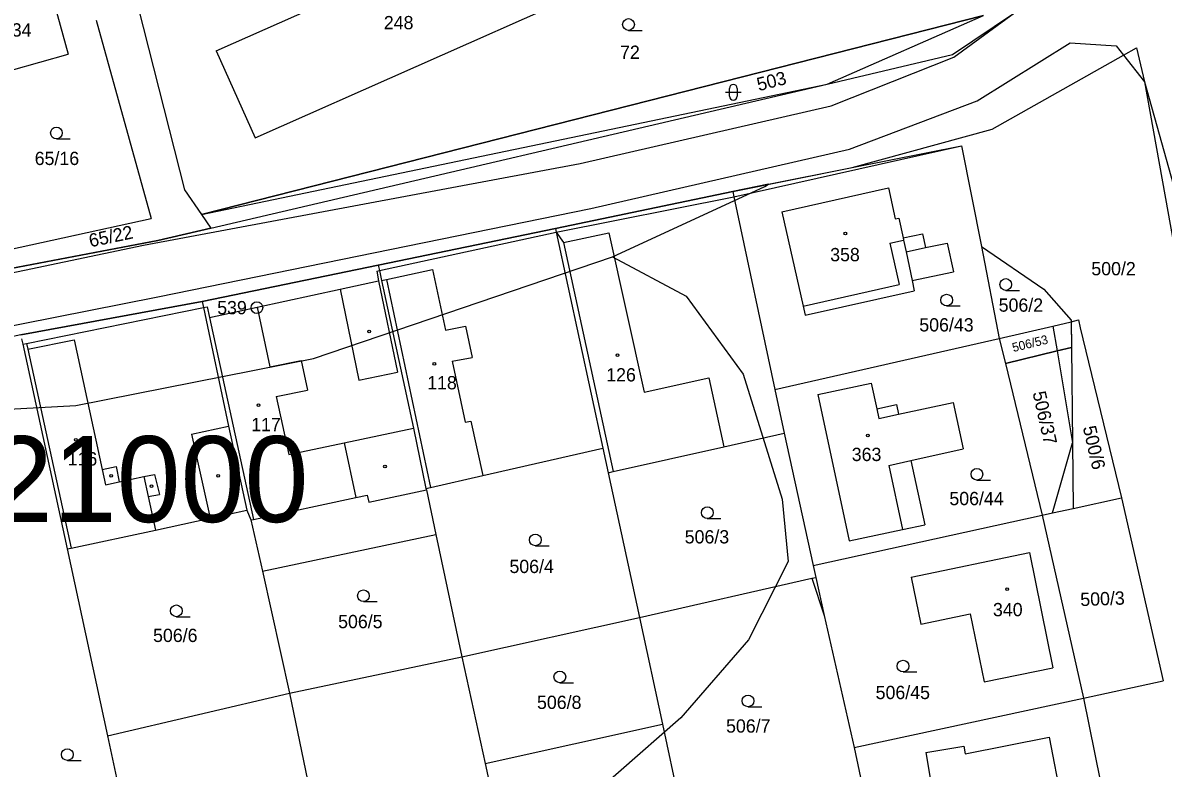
# Model space of a CAD drawing. Extents: x -725765 to -723182, y -1052705 to -1049154.
# Drawn here: x -724834.1 to -724688.1, y -1051176.5 to -1051081 of the extents above; entities that cross this region are included whole.
import ezdxf

# ---------------------------------------------------------------- set-up
doc = ezdxf.new("R2010")
doc.units = 0
for name, color, linetype in [('Vrstva 1', 7, 'Continuous'), ('Vrstva 17', 7, 'Continuous'), ('Vrstva 18', 7, 'Continuous'), ('Vrstva 19', 7, 'Continuous'), ('Vrstva 25', 7, 'Continuous'), ('Vrstva 4', 7, 'Continuous'), ('Vrstva 52', 7, 'Continuous'), ('Vrstva 53', 7, 'Continuous')]:
    doc.layers.add(name, color=color, linetype=linetype)

msp = doc.modelspace()

# ---------------------------------------------------------------- linework, layer by layer
at = {"layer": 'Vrstva 1'}
for points in [[(-724809.35, -1051084.62), (-724768.06, -1051066.29)], [(-724831.04, -1051075.08), (-724828.29, -1051085.04)], [(-724804.38, -1051095.73), (-724763.12, -1051077.44)], [(-724819.35, -1051079.05), (-724813.42, -1051102.39)], [(-724811.24, -1051105.56), (-724711.14, -1051080.07)], [(-724715.11, -1051085.06), (-724707.16, -1051079.74)], [(-724824.72, -1051080.67), (-724817.68, -1051106.09)], [(-724809.35, -1051084.62), (-724804.38, -1051095.73)], [(-724693.2, -1051085.16), (-724691.55, -1051084.23)], [(-724691.55, -1051084.23), (-724690.5, -1051088.58)], [(-724839.24, -1051088.1), (-724828.29, -1051085.04)], [(-724731.15, -1051088.89), (-724715.11, -1051085.06)], [(-724710, -1051094.64), (-724693.2, -1051085.16)], [(-724810.03, -1051107.31), (-724731.15, -1051088.89)], [(-724690.5, -1051088.58), (-724681.95, -1051136.24)], [(-724727.92, -1051099.55), (-724710, -1051094.64)], [(-724727.92, -1051099.55), (-724713.93, -1051096.76)], [(-724713.93, -1051096.76), (-724711.4, -1051109.67)], [(-724743.22, -1051102.61), (-724727.92, -1051099.55)], [(-724736.92, -1051105.21), (-724723.3, -1051102.15)], [(-724723.3, -1051102.15), (-724722.41, -1051106.12)], [(-724813.42, -1051102.39), (-724811.24, -1051105.56)], [(-724765.92, -1051107.34), (-724743.22, -1051102.61)], [(-724743.22, -1051102.61), (-724743.07, -1051103.29)], [(-724743.07, -1051103.29), (-724737.83, -1051127.97)], [(-724837.23, -1051110.34), (-724817.68, -1051106.09)], [(-724811.24, -1051105.56), (-724810.03, -1051107.31)], [(-724736.92, -1051105.21), (-724734.22, -1051117.3)], [(-724722.41, -1051106.12), (-724721.96, -1051106.02)], [(-724721.96, -1051106.02), (-724721.42, -1051108.55)], [(-724816.84, -1051108.91), (-724810.03, -1051107.31)], [(-724788.6, -1051112.06), (-724765.92, -1051107.34)], [(-724765.92, -1051107.34), (-724765.81, -1051107.83)], [(-724765.81, -1051107.83), (-724759.85, -1051135.47)], [(-724721.42, -1051108.55), (-724718.93, -1051108.02)], [(-724718.93, -1051108.02), (-724718.53, -1051109.81)], [(-724856.27, -1051116.41), (-724816.84, -1051108.91)], [(-724718.53, -1051109.81), (-724715.76, -1051109.22)], [(-724715.76, -1051109.22), (-724714.98, -1051112.91)], [(-724711.4, -1051109.67), (-724709.1, -1051121.42)], [(-724711.4, -1051109.67), (-724703.4, -1051115.12)], [(-724811.15, -1051116.69), (-724788.6, -1051112.06)], [(-724788.6, -1051112.06), (-724788.45, -1051112.73)], [(-724788.45, -1051112.73), (-724788.18, -1051114.02)], [(-724720.26, -1051114.03), (-724714.98, -1051112.91)], [(-724788.18, -1051114.02), (-724784.08, -1051132.92)], [(-724733.96, -1051118.47), (-724719.98, -1051115.35)], [(-724720.26, -1051114.03), (-724719.98, -1051115.35)], [(-724703.4, -1051115.12), (-724699.9, -1051119.09)], [(-724834.36, -1051120.96), (-724811.15, -1051116.69)], [(-724811.15, -1051116.69), (-724810.98, -1051117.47)], [(-724810.98, -1051117.47), (-724807.77, -1051132.66)], [(-724734.22, -1051117.3), (-724733.96, -1051118.47)], [(-724702.24, -1051119.86), (-724699.9, -1051119.29)], [(-724699.9, -1051119.29), (-724698.97, -1051119.07)], [(-724699.9, -1051119.09), (-724699.9, -1051119.29)], [(-724699.9, -1051119.29), (-724699.86, -1051122.59)], [(-724698.97, -1051119.07), (-724698.73, -1051120.08)], [(-724709.1, -1051121.42), (-724702.24, -1051119.86)], [(-724698.73, -1051120.08), (-724697.67, -1051124.45)], [(-724834.26, -1051121.49), (-724834.1, -1051122.17)], [(-724834.1, -1051122.17), (-724828.43, -1051148.39)], [(-724737.83, -1051127.97), (-724709.1, -1051121.42)], [(-724709.1, -1051121.42), (-724708.32, -1051124.64)], [(-724701.71, -1051123.04), (-724699.86, -1051122.59)], [(-724699.86, -1051122.59), (-724699.73, -1051134.81)], [(-724708.32, -1051124.64), (-724701.71, -1051123.04)], [(-724708.32, -1051124.64), (-724703.63, -1051144.06)], [(-724697.67, -1051124.45), (-724693.47, -1051141.84)], [(-724737.83, -1051127.97), (-724736.62, -1051133.56)], [(-724732.33, -1051128.6), (-724725.49, -1051127.14)], [(-724725.49, -1051127.14), (-724724.79, -1051130.43)], [(-724732.33, -1051128.6), (-724728.32, -1051147.36)], [(-724724.79, -1051130.43), (-724722.25, -1051129.88)], [(-724722.25, -1051129.88), (-724721.99, -1051131.13)], [(-724721.99, -1051131.13), (-724715.02, -1051129.64)], [(-724715.02, -1051129.64), (-724713.74, -1051135.58)], [(-724807.77, -1051132.66), (-724805.44, -1051143.42)], [(-724784.08, -1051132.92), (-724782.5, -1051140.64)], [(-724744.38, -1051135.3), (-724736.62, -1051133.56)], [(-724736.62, -1051133.56), (-724732.94, -1051150.5)], [(-724775.23, -1051138.98), (-724759.85, -1051135.47)], [(-724759.85, -1051135.47), (-724759.17, -1051138.62)], [(-724758.54, -1051138.48), (-724744.38, -1051135.3)], [(-724720.41, -1051137.07), (-724713.74, -1051135.58)], [(-724699.73, -1051134.81), (-724699.66, -1051143.2)], [(-724720.41, -1051137.07), (-724718.63, -1051145.28)], [(-724759.17, -1051138.62), (-724758.54, -1051138.48)], [(-724759.17, -1051138.62), (-724755.18, -1051157.14)], [(-724781.93, -1051140.51), (-724775.23, -1051138.98)], [(-724782.5, -1051140.64), (-724781.93, -1051140.51)], [(-724782.5, -1051140.64), (-724782.43, -1051140.83)], [(-724782.43, -1051140.83), (-724781.24, -1051146.54)], [(-724699.66, -1051143.2), (-724693.47, -1051141.84)], [(-724693.47, -1051141.84), (-724688.13, -1051165.29)], [(-724817.13, -1051146), (-724810.13, -1051144.44)], [(-724810.13, -1051144.44), (-724805.44, -1051143.42)], [(-724805.44, -1051143.42), (-724804.9, -1051144.67)], [(-724732.94, -1051150.5), (-724703.63, -1051144.06)], [(-724703.63, -1051144.06), (-724702.31, -1051143.78)], [(-724703.63, -1051144.06), (-724698.31, -1051167.47)], [(-724702.31, -1051143.78), (-724699.66, -1051143.2)], [(-724827.92, -1051148.28), (-724817.13, -1051146)], [(-724804.9, -1051144.67), (-724803.44, -1051151.22)], [(-724728.32, -1051147.36), (-724721.49, -1051145.9)], [(-724721.49, -1051145.9), (-724718.63, -1051145.28)], [(-724803.44, -1051151.22), (-724781.24, -1051146.54)], [(-724781.24, -1051146.54), (-724777.9, -1051162.19)], [(-724828.43, -1051148.39), (-724827.92, -1051148.28)], [(-724828.43, -1051148.39), (-724823.26, -1051172.32)], [(-724720.39, -1051151.98), (-724705.23, -1051148.84)], [(-724705.23, -1051148.84), (-724702.23, -1051163.61)], [(-724803.44, -1051151.22), (-724799.95, -1051166.84)], [(-724732.94, -1051150.5), (-724732.6, -1051152.02)], [(-724755.18, -1051157.14), (-724733.1, -1051152.13)], [(-724733.1, -1051152.13), (-724732.6, -1051152.02)], [(-724732.6, -1051152.02), (-724731.5, -1051156.9)], [(-724720.39, -1051151.98), (-724719.14, -1051158)], [(-724777.9, -1051162.19), (-724755.18, -1051157.14)], [(-724755.18, -1051157.14), (-724752.23, -1051170.8)], [(-724731.5, -1051156.9), (-724727.67, -1051173.8)], [(-724719.14, -1051158), (-724712.82, -1051156.7)], [(-724712.82, -1051156.7), (-724711.03, -1051165.4)], [(-724799.95, -1051166.84), (-724777.9, -1051162.19)], [(-724777.9, -1051162.19), (-724774.92, -1051175.87)], [(-724711.03, -1051165.4), (-724702.23, -1051163.61)], [(-724698.31, -1051167.47), (-724688.13, -1051165.29)], [(-724823.26, -1051172.32), (-724799.95, -1051166.84)], [(-724799.95, -1051166.84), (-724792.53, -1051202.73)], [(-724727.67, -1051173.8), (-724698.31, -1051167.47)], [(-724698.31, -1051167.47), (-724694.07, -1051188.55)], [(-724774.92, -1051175.87), (-724752.23, -1051170.8)], [(-724752.23, -1051170.8), (-724750.11, -1051180.63)], [(-724823.26, -1051172.32), (-724815.69, -1051207.56)], [(-724718.51, -1051174.45), (-724713.64, -1051173.62)], [(-724713.64, -1051173.62), (-724713.47, -1051174.61)], [(-724713.47, -1051174.61), (-724702.7, -1051172.47)], [(-724702.7, -1051172.47), (-724701.12, -1051180.66)], [(-724727.67, -1051173.8), (-724726.11, -1051181.27)], [(-724718.51, -1051174.45), (-724716.44, -1051186.62)], [(-724774.92, -1051175.87), (-724772.81, -1051185.53)]]:
    msp.add_lwpolyline(points, dxfattribs=at)
at = {"layer": 'Vrstva 25'}
for points in [[(-724756.57, -1051081.99), (-724754.82, -1051081.99)], [(-724744.14, -1051089.92), (-724742.14, -1051089.92)], [(-724743.64, -1051090.42), (-724743.64, -1051089.42)], [(-724742.64, -1051089.42), (-724742.64, -1051090.42)], [(-724829.8, -1051095.88), (-724828.05, -1051095.88)], [(-724708.27, -1051115.28), (-724706.52, -1051115.28)], [(-724715.84, -1051117.27), (-724714.09, -1051117.27)], [(-724711.97, -1051139.57), (-724710.22, -1051139.57)], [(-724746.48, -1051144.49), (-724744.73, -1051144.49)], [(-724768.49, -1051147.98), (-724766.74, -1051147.98)], [(-724790.5, -1051155.13), (-724788.75, -1051155.13)], [(-724814.45, -1051157.06), (-724812.7, -1051157.06)], [(-724721.42, -1051164.13), (-724719.67, -1051164.13)], [(-724765.36, -1051165.52), (-724763.61, -1051165.52)], [(-724741.27, -1051168.59), (-724739.52, -1051168.59)], [(-724828.4, -1051175.46), (-724826.65, -1051175.46)]]:
    msp.add_lwpolyline(points, dxfattribs=at)
for centre, radius in [((-724756.57, -1051081.24), 0.75), ((-724829.8, -1051095.13), 0.75), ((-724728.81, -1051108), 0.175), ((-724708.27, -1051114.53), 0.75), ((-724804.14, -1051117.49), 0.75), ((-724715.84, -1051116.52), 0.75), ((-724804.14, -1051117.49), 0.032), ((-724789.75, -1051120.54), 0.175), ((-724757.98, -1051123.57), 0.175), ((-724781.42, -1051124.7), 0.175), ((-724803.95, -1051129.99), 0.175), ((-724827.3, -1051134.4), 0.175), ((-724725.92, -1051133.87), 0.175), ((-724787.74, -1051137.83), 0.175), ((-724711.97, -1051138.82), 0.75), ((-724822.8, -1051139.04), 0.175), ((-724809.08, -1051139.02), 0.175), ((-724817.62, -1051140.36), 0.175), ((-724746.48, -1051143.74), 0.75), ((-724768.49, -1051147.23), 0.75), ((-724790.5, -1051154.38), 0.75), ((-724708.1, -1051153.55), 0.175), ((-724814.45, -1051156.31), 0.75), ((-724721.42, -1051163.38), 0.75), ((-724765.36, -1051164.77), 0.75), ((-724741.27, -1051167.84), 0.75), ((-724828.4, -1051174.71), 0.75)]:
    msp.add_circle(centre, radius, dxfattribs=at)
for centre, start, end in [((-724743.14, -1051089.42), 0.101, 180.0014), ((-724743.14, -1051090.42), 180.1024, 0.0029)]:
    msp.add_arc(centre, 0.5, start, end, dxfattribs=at)
at = {"layer": 'Vrstva 4'}
for points in [[(-724731.15, -1051088.89), (-724711.14, -1051080.07)], [(-724714.92, -1051085.41), (-724707.16, -1051079.74)], [(-724711.95, -1051091), (-724700.02, -1051083.57)], [(-724700.02, -1051083.57), (-724694.14, -1051083.96)], [(-724694.14, -1051083.96), (-724693.2, -1051085.16)], [(-724730.63, -1051091.64), (-724714.92, -1051085.41)], [(-724693.2, -1051085.16), (-724690.5, -1051088.58)], [(-724811.24, -1051105.56), (-724731.15, -1051088.89)], [(-724690.5, -1051088.58), (-724683.08, -1051115.08)], [(-724762.76, -1051099.03), (-724730.63, -1051091.64)], [(-724728.29, -1051097.2), (-724711.95, -1051091)], [(-724761.37, -1051104.81), (-724728.29, -1051097.2)], [(-724743.07, -1051103.29), (-724713.93, -1051096.76)], [(-724818.67, -1051109.51), (-724762.76, -1051099.03)], [(-724765.81, -1051107.83), (-724743.07, -1051103.29)], [(-724816.84, -1051116.09), (-724761.37, -1051104.81)], [(-724788.45, -1051112.73), (-724765.81, -1051107.83)], [(-724765.81, -1051107.83), (-724764.88, -1051109.16)], [(-724764.88, -1051109.16), (-724759.09, -1051107.92)], [(-724759.09, -1051107.92), (-724754.58, -1051128.3)], [(-724849.16, -1051115.88), (-724818.67, -1051109.51)], [(-724764.88, -1051109.16), (-724758.54, -1051138.48)], [(-724723.11, -1051109.22), (-724721.36, -1051108.83)], [(-724723.11, -1051109.22), (-724721.92, -1051114.54)], [(-724721.42, -1051108.55), (-724721.36, -1051108.83)], [(-724721.36, -1051108.83), (-724721.04, -1051110.34)], [(-724721.04, -1051110.34), (-724718.53, -1051109.81)], [(-724721.04, -1051110.34), (-724720.26, -1051114.03)], [(-724788.8, -1051112.82), (-724788.45, -1051112.73)], [(-724788.8, -1051112.82), (-724788.57, -1051114.07)], [(-724788.18, -1051114.02), (-724787.55, -1051113.88)], [(-724787.55, -1051113.88), (-724781.64, -1051112.6)], [(-724787.55, -1051113.88), (-724781.93, -1051140.51)], [(-724781.64, -1051112.6), (-724779.99, -1051120.36)], [(-724804.12, -1051117.44), (-724793.49, -1051115.13)], [(-724793.49, -1051115.13), (-724788.57, -1051114.07)], [(-724793.49, -1051115.13), (-724791.07, -1051126.79)], [(-724788.57, -1051114.07), (-724786.12, -1051125.76)], [(-724734.22, -1051117.3), (-724721.92, -1051114.54)], [(-724847.23, -1051122.13), (-724816.84, -1051116.09)], [(-724833.64, -1051122.08), (-724810.98, -1051117.47)], [(-724810.98, -1051117.47), (-724810.51, -1051117.37)], [(-724810.51, -1051117.37), (-724810.21, -1051118.74)], [(-724810.21, -1051118.74), (-724804.12, -1051117.44)], [(-724804.12, -1051117.44), (-724802.48, -1051125.05)], [(-724810.21, -1051118.74), (-724804.56, -1051144.6)], [(-724779.99, -1051120.36), (-724777.43, -1051119.87)], [(-724777.43, -1051119.87), (-724776.6, -1051123.88)], [(-724702.24, -1051119.86), (-724701.71, -1051123.04)], [(-724834.1, -1051122.17), (-724833.64, -1051122.08)], [(-724833.64, -1051122.08), (-724833.48, -1051122.82)], [(-724833.48, -1051122.82), (-724827.53, -1051121.62)], [(-724827.53, -1051121.62), (-724823.93, -1051138.23)], [(-724833.48, -1051122.82), (-724827.92, -1051148.28)], [(-724779.15, -1051124.34), (-724776.6, -1051123.88)], [(-724701.71, -1051123.04), (-724699.73, -1051134.81)], [(-724802.48, -1051125.05), (-724798.49, -1051124.24)], [(-724798.49, -1051124.24), (-724797.66, -1051128.04)], [(-724779.15, -1051124.34), (-724777.49, -1051132.17)], [(-724791.07, -1051126.79), (-724786.12, -1051125.76)], [(-724754.58, -1051128.3), (-724746.29, -1051126.47)], [(-724746.29, -1051126.47), (-724744.38, -1051135.3)], [(-724801.67, -1051128.85), (-724797.66, -1051128.04)], [(-724801.67, -1051128.85), (-724800.07, -1051136.29)], [(-724724.79, -1051130.43), (-724724.53, -1051131.68)], [(-724724.53, -1051131.68), (-724721.99, -1051131.13)], [(-724812.49, -1051133.69), (-724807.77, -1051132.66)], [(-724777.49, -1051132.17), (-724776.75, -1051132.01)], [(-724776.75, -1051132.01), (-724775.23, -1051138.98)], [(-724812.49, -1051133.69), (-724810.13, -1051144.44)], [(-724792.96, -1051134.79), (-724784.08, -1051132.92)], [(-724800.07, -1051136.29), (-724792.96, -1051134.79)], [(-724792.96, -1051134.79), (-724791.47, -1051141.81)], [(-724702.31, -1051143.78), (-724699.73, -1051134.81)], [(-724723.26, -1051137.71), (-724720.41, -1051137.07)], [(-724823.93, -1051138.23), (-724822.17, -1051137.81)], [(-724823.93, -1051138.23), (-724823.51, -1051140.16)], [(-724822.17, -1051137.81), (-724821.77, -1051139.79)], [(-724723.26, -1051137.71), (-724721.49, -1051145.9)], [(-724823.51, -1051140.16), (-724821.77, -1051139.79)], [(-724821.77, -1051139.79), (-724818.6, -1051139.1)], [(-724818.6, -1051139.1), (-724817.25, -1051138.85)], [(-724818.6, -1051139.1), (-724818.05, -1051141.68)], [(-724817.25, -1051138.85), (-724816.6, -1051141.43)], [(-724818.05, -1051141.68), (-724816.6, -1051141.43)], [(-724791.47, -1051141.81), (-724790.04, -1051141.51)], [(-724790.04, -1051141.51), (-724789.83, -1051142.4)], [(-724789.83, -1051142.4), (-724782.43, -1051140.83)], [(-724818.05, -1051141.68), (-724817.13, -1051146)], [(-724804.56, -1051144.6), (-724791.47, -1051141.81)], [(-724804.9, -1051144.67), (-724804.56, -1051144.6)], [(-724733.1, -1051152.13), (-724731.5, -1051156.9)]]:
    msp.add_lwpolyline(points, dxfattribs=at)
at = {"layer": 'Vrstva 52'}
for points in [[(-724711.14, -1051080.07), (-724811.24, -1051105.56), (-724810.03, -1051107.31), (-724816.84, -1051108.91), (-724856.27, -1051116.41), (-724925.34, -1051132.13), (-724935.23, -1051134.64), (-724936.98, -1051135.08), (-725011.19, -1051159.63), (-725057.43, -1051172.97), (-725105.34, -1051186.54), (-725152.07, -1051199.14), (-725159.2, -1051200.55), (-725166.37, -1051202.6), (-725179.86, -1051206.45), (-725205.38, -1051213.74), (-725231.72, -1051221.15), (-725243.81, -1051225.51), (-725272.4, -1051235.81), (-725277.83, -1051237.87), (-725301.81, -1051246.05), (-725340.64, -1051260.21)], [(-724738.66, -1051101.7), (-724727.92, -1051099.55), (-724713.93, -1051096.76), (-724711.4, -1051109.67), (-724703.4, -1051115.12), (-724699.9, -1051119.09), (-724699.86, -1051122.59), (-724701.71, -1051123.04), (-724708.32, -1051124.64), (-724703.63, -1051144.06), (-724698.31, -1051167.47), (-724694.07, -1051188.55), (-724706.63, -1051197.83), (-724702.61, -1051206.23), (-724701.35, -1051206.43), (-724710.06, -1051240.15), (-724713.53, -1051258.05), (-724715.78, -1051272.09), (-724717.04, -1051281.38), (-724719.01, -1051298.44), (-724720.73, -1051298.85), (-724723.66, -1051347.54)], [(-724738.66, -1051101.7), (-724743.22, -1051102.61), (-724765.92, -1051107.34), (-724788.6, -1051112.06), (-724811.15, -1051116.69), (-724834.36, -1051120.96), (-724845.44, -1051123.38), (-724860.72, -1051126.71), (-724884.18, -1051130.69), (-724904.47, -1051135.61), (-724926.75, -1051141.34), (-724930.97, -1051142.63), (-724948.22, -1051147.9), (-724958.02, -1051151.55), (-724968.47, -1051155.44), (-724973.12, -1051157.17), (-724973.59, -1051157.32), (-725009.19, -1051168.73), (-725008.93, -1051169.9)], [(-724758.63, -1051111), (-724739.13, -1051102), (-724738.66, -1051101.7)], [(-724758.63, -1051111), (-724749.19, -1051116), (-724741.88, -1051126), (-724736.88, -1051142), (-724736.13, -1051150), (-724741.19, -1051160), (-724749.88, -1051170), (-724773.81, -1051191), (-724798.38, -1051209), (-724824.48, -1051226.57), (-724825.13, -1051227), (-724846.13, -1051236), (-724881.19, -1051243), (-724916.63, -1051250), (-724936.36, -1051260.92), (-724938.31, -1051262), (-724956.38, -1051276), (-724978.13, -1051299), (-724980.17, -1051301.45), (-725000, -1051325.25)], [(-724944.63, -1051155), (-724922.81, -1051149), (-724888.13, -1051139), (-724873.63, -1051136), (-724845.38, -1051131), (-724827.31, -1051130), (-724796.88, -1051124), (-724758.63, -1051111)]]:
    msp.add_lwpolyline(points, dxfattribs=at)

# ---------------------------------------------------------------- texts
at = {"layer": 'Vrstva 17'}
msp.add_text('539', height=1.7, dxfattribs=at).set_placement((-724809.22, -1051118.34))
at = {"layer": 'Vrstva 18'}
for s, p in [('72', (-724757.65, -1051085.64)), ('65/16', (-724832.58, -1051099.23)), ('500/2', (-724697.32, -1051113.35)), ('506/2', (-724709.18, -1051118.01)), ('506/43', (-724719.34, -1051120.54)), ('506/44', (-724715.49, -1051142.78)), ('506/3', (-724749.37, -1051147.68)), ('506/4', (-724771.81, -1051151.47)), ('506/5', (-724793.74, -1051158.53)), ('506/6', (-724817.43, -1051160.3)), ('506/45', (-724724.93, -1051167.61)), ('506/8', (-724768.28, -1051168.87)), ('506/7', (-724744.08, -1051171.9))]:
    msp.add_text(s, height=1.7, dxfattribs=at).set_placement(p)
for s, height, rotation, p in [('503', 1.7, 14.4001, (-724739.89, -1051089.78)), ('65/22', 1.7, 11.8001, (-724825.45, -1051109.77)), ('506/53', 1.14, 13.7001, (-724707.3, -1051123.18)), ('506/37', 1.7, 282.6022, (-724704.85, -1051128.39)), ('500/6', 1.7, 283.0023, (-724698.42, -1051132.82)), ('500/3', 1.7, 2.1, (-724698.7, -1051155.71))]:
    msp.add_text(s, height=height, rotation=rotation, dxfattribs=at).set_placement(p)
at = {"layer": 'Vrstva 19'}
for s, p in [('248', (-724787.89, -1051081.85)), ('234', (-724836.78, -1051082.78)), ('358', (-724730.75, -1051111.55)), ('126', (-724759.42, -1051126.94)), ('118', (-724782.34, -1051127.95)), ('117', (-724804.87, -1051133.31)), ('363', (-724727.99, -1051137.13)), ('116', (-724828.37, -1051137.7)), ('340', (-724709.91, -1051157))]:
    msp.add_text(s, height=1.7, dxfattribs=at).set_placement(p)
at = {"layer": 'Vrstva 53'}
msp.add_text('21000', height=11, dxfattribs=at).set_placement((-724838.44, -1051144.94))

doc.saveas('drawing.dxf')
